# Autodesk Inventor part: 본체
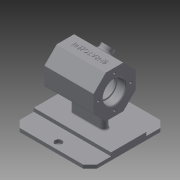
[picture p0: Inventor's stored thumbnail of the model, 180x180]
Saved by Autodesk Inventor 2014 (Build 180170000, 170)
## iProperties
Created: 2018-06
Part Number: 본체
Material: Generic
Document SubType Name: Modeling
Designer: kh
Density: 1 g/cm^3
Appearance: Default
Author: kh
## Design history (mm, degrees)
sketch "Sketch1"
  geometry: L1 (55, 55)-(-55, 55); L2 (-55, 55)-(-55, -55); L3 (-55, -55)-(55, -55); L4 (55, -55)-(55, 55); L5 (55, 55)-(-55, -55); L6 (-55, 55)-(55, -55); 1 further point
  constraints: 12 end point, 2 midpoint, 2 parallel, 1 horizontal, 1 perpendicular
  dimensions: "d0" = 110 distance of L1.start L1.end; "d1" = 110 distance of L1.end L2.end
extrude "Extrusion1" new body sketch "Sketch1" distance "d2" = 5; taper "d3" = 0 deg
sketch "Sketch2"
  geometry: L1 (55, 25)-(-55, 25); L2 (-55, 25)-(-55, -25); L3 (-55, -25)-(55, -25); L4 (55, -25)-(55, 25); L5 (55, 25)-(-55, -25); L6 (-55, 25)-(55, -25); 1 further point
  constraints: 12 end point, 2 midpoint, 2 parallel, 1 horizontal, 1 perpendicular
  dimensions: "d4" = 50 distance of L1.end L2.end; "d5" = 110 distance of L1.start L1.end
extrude "Extrusion2" join sketch "Sketch2" distance "d6" = 5; taper "d7" = 0 deg
sketch "Sketch3"
  geometry: L1 (55, 25)-(-55, 25) reference; L2 (-55, 25)-(-55, -25) reference; L3 (-55, -25)-(55, -25) reference; L4 (55, -25)-(55, 25) reference; L5 (-55, 0)-(55, 0); L6 (55, 55)-(-55, 55) reference; 4 further points
  constraints: 3 midpoint, 2 end point, 1 symmetric about line, 1 vertical alignment
  dimensions: "d8" = 10 distance from line of point (0, 45) L6
hole "Hole1" sketch "Sketch3" at (0, 45), (0, -45) diameter "d9" = 10; stored, may be unused: countersink angle "d13" = 90 deg, drill point angle "d15" = 118 deg; dims "d10" = 6, "d11" = 4, "d12" = 2, "d14" = 8
chamfer "Chamfer1" distance "d16" = 10; stored, may be unused: second distance "d17" = 2, angle "d18" = 45 deg
workplane "Work Plane2"
sketch "Sketch6" dims "d25" = 60
  geometry: L1 (-45, 0)-(45, 0) reference; L2 (12.426, 92)-(30, 74.426); L3 (30, 74.426)-(30, 49.574); L4 (30, 49.574)-(12.426, 32); L5 (12.426, 32)-(-12.426, 32); L6 (-12.426, 32)-(-30, 49.574); L7 (-30, 49.574)-(-30, 74.426); L8 (-30, 74.426)-(-12.426, 92); L9 (-12.426, 92)-(12.426, 92); 7 further points
  constraints: 16 end point, 3 coincident, 3 vertical alignment, 2 midpoint, 19 other
  dimensions: "d26" = 62 distance from line of L1 point (0, 62)
extrude "Extrusion3" join sketch "Sketch6" distance "d27" = 70; taper "d28" = 0 deg
sketch "Sketch8"
  geometry: L1 (92, 12.426)-(92, -12.426) reference; L2 (74.426, 30)-(92, 12.426) reference; L3 (49.574, 30)-(74.426, 30) reference; L4 (32, 12.426)-(49.574, 30) reference; L5 (32, -12.426)-(32, 12.426) reference; L6 (49.574, -30)-(32, -12.426) reference; L7 (74.426, -30)-(49.574, -30) reference; L8 (92, -12.426)-(74.426, -30) reference; L9 (32, 0)-(92, 0); C1 r 16 at (62, 0); 2 further points
  constraints: 3 midpoint, 2 end point, 1 centre point, 1 coincident
  dimensions: "d29" = 32 diameter of C1
extrude "Extrusion4" cut sketch "Sketch8" distance "d30" = 12; taper "d31" = 0 deg
sketch "Sketch9"
  geometry: C1 r 16 at (0, 0) reference; C2 r 14 at (0, 0); 1 further point
  constraints: 1 centre point, 1 coincident
  dimensions: "d32" = 28 diameter of C2
extrude "Extrusion5" cut sketch "Sketch9" distance "d33" = 3; taper "d34" = 0 deg
sketch "Sketch10"
  geometry: C1 r 14 at (0, 0) reference; C2 r 25 at (0, 0); 1 further point
  constraints: 1 centre point, 1 coincident
  dimensions: "d35" = 50 diameter of C2
extrude "Extrusion6" cut sketch "Sketch10" distance "d36" = 40; taper "d37" = 0 deg
sketch "Sketch11"
  geometry: C1 r 25 at (-62, 0) reference; C2 r 16 at (-62, 0); 1 further point
  constraints: 1 centre point, 1 coincident
  dimensions: "d38" = 32 diameter of C2
extrude "Extrusion7" cut sketch "Sketch11" distance "d39" = 12; taper "d40" = 0 deg
sketch "Sketch12"
  geometry: C1 r 16 at (0, 0) reference; C2 r 14 at (0, 0); 1 further point
  constraints: 1 centre point, 1 coincident
  dimensions: "d41" = 28 diameter of C2
extrude "Extrusion8" cut sketch "Sketch12" distance "d42" = 3; taper "d43" = 0 deg
sketch "Sketch13" dims "d44" = 46
  geometry: L1 (-92, 12.426)-(-92, -12.426) reference; L2 (-92, -12.426)-(-74.426, -30) reference; L3 (-74.426, -30)-(-49.574, -30) reference; L4 (-49.574, -30)-(-32, -12.426) reference; L5 (-32, -12.426)-(-32, 12.426) reference; L6 (-32, 12.426)-(-49.574, 30) reference; L7 (-49.574, 30)-(-74.426, 30) reference; L8 (-74.426, 30)-(-92, 12.426) reference; L9 (-62, 0)-(-85, 0); C1 r 16 at (-62, 0) reference; 2 further points
  constraints: 2 coincident, 2 end point, 1 horizontal alignment, 1 parallel, 2 other
hole "Hole2" sketch "Sketch13" at (-85, 0) diameter "d45" = 3.459; stored, may be unused: countersink angle "d49" = 90 deg, drill point angle "d51" = 118 deg; dims "d46" = 8, "d47" = 4, "d48" = 2, "d50" = 10
pattern_circular "Circular Pattern1" dims angle "d53" = 360 deg
workplane "Work Plane4"
mirror "Mirror1"
sketch "Sketch14"
  geometry: L1 (-62, 0)-(-97.146, 0); L2 (-62, 0)-(-88.163, 26.163); L3 (-74.426, 30)-(-92, 12.426) reference; L4 (-81.69, 32.636)-(-94.636, 19.69); C1 r 14 at (-62, 0) reference; C2 r 25 at (-62, 0) reference; 1 further point
  constraints: 6 end point, 1 horizontal, 1 midpoint, 1 parallel
  dimensions: "d56" = 45 deg angle of L2 L1; "d57" = 7 distance from line of L2.end L3
  node "Projected Loop7"
workplane "Work Plane5"
sketch "Sketch15"
  geometry: L1 (0, 9.154)-(0, -9.154) reference; C1 r 8 at (0, 0); 1 further point
  constraints: 1 centre point, 1 midpoint
  dimensions: "d58" = 16 diameter of C1
extrude "Extrusion9" join sketch "Sketch15" stored distance "d59" = 3; taper "d60" = 0 deg
hole "Hole3" diameter "d63" = 8; stored, may be unused: countersink angle "d67" = 90 deg, drill point angle "d69" = 0 deg; dims "d61" = 10, "d62" = 10, "d64" = 8, "d65" = 4, "d66" = 2, "d68" = 10
chamfer "Chamfer2" distance "d70" = 1; stored, may be unused: second distance "d71" = 2, angle "d72" = 45 deg
fillet "Fillet2" dims "d74" = 3
sketch "Sketch16"
  geometry: L1 (-19, 0)-(19, 0); L2 (-19, 5)-(19, 5); L3 (19, -5)-(-19, -5); A1 r 5 centre (-19, 0) between (-19, 5) and (-19, -5); A2 r 5 centre (19, 0) between (19, -5) and (19, 5); 2 further points
  constraints: 8 end point, 4 point on circle, 4 tangent, 2 centre point, 1 coincident, 1 horizontal, 1 midpoint, 1 parallel
  dimensions: "d75" = 38 distance of L1.end L1.start; "d76" = 5 radius of A1
extrude "Extrusion10" join sketch "Sketch16" stored distance "d77" = 0; taper "d78" = 0 deg
fillet "Fillet3" dims "d79" = 2
sketch "Sketch17"
  geometry: 2 further points
  constraints: 1 coincident, 1 other
emboss "Emboss1" sketch "Sketch17" dims "d0" = 110, "d1" = 110, "d80" = 0.5, "d81" = 0
fillet "Fillet4" dims "d82" = 0.3
fillet "Fillet5" dims "d83" = 1
body "Solid1"
node "Projected Loop1"
node "Projected Loop2"
node "Projected Loop3"
node "Projected Loop4"
node "Projected Loop5"
node "Projected Loop6"
other parameters: "d22" = -35
